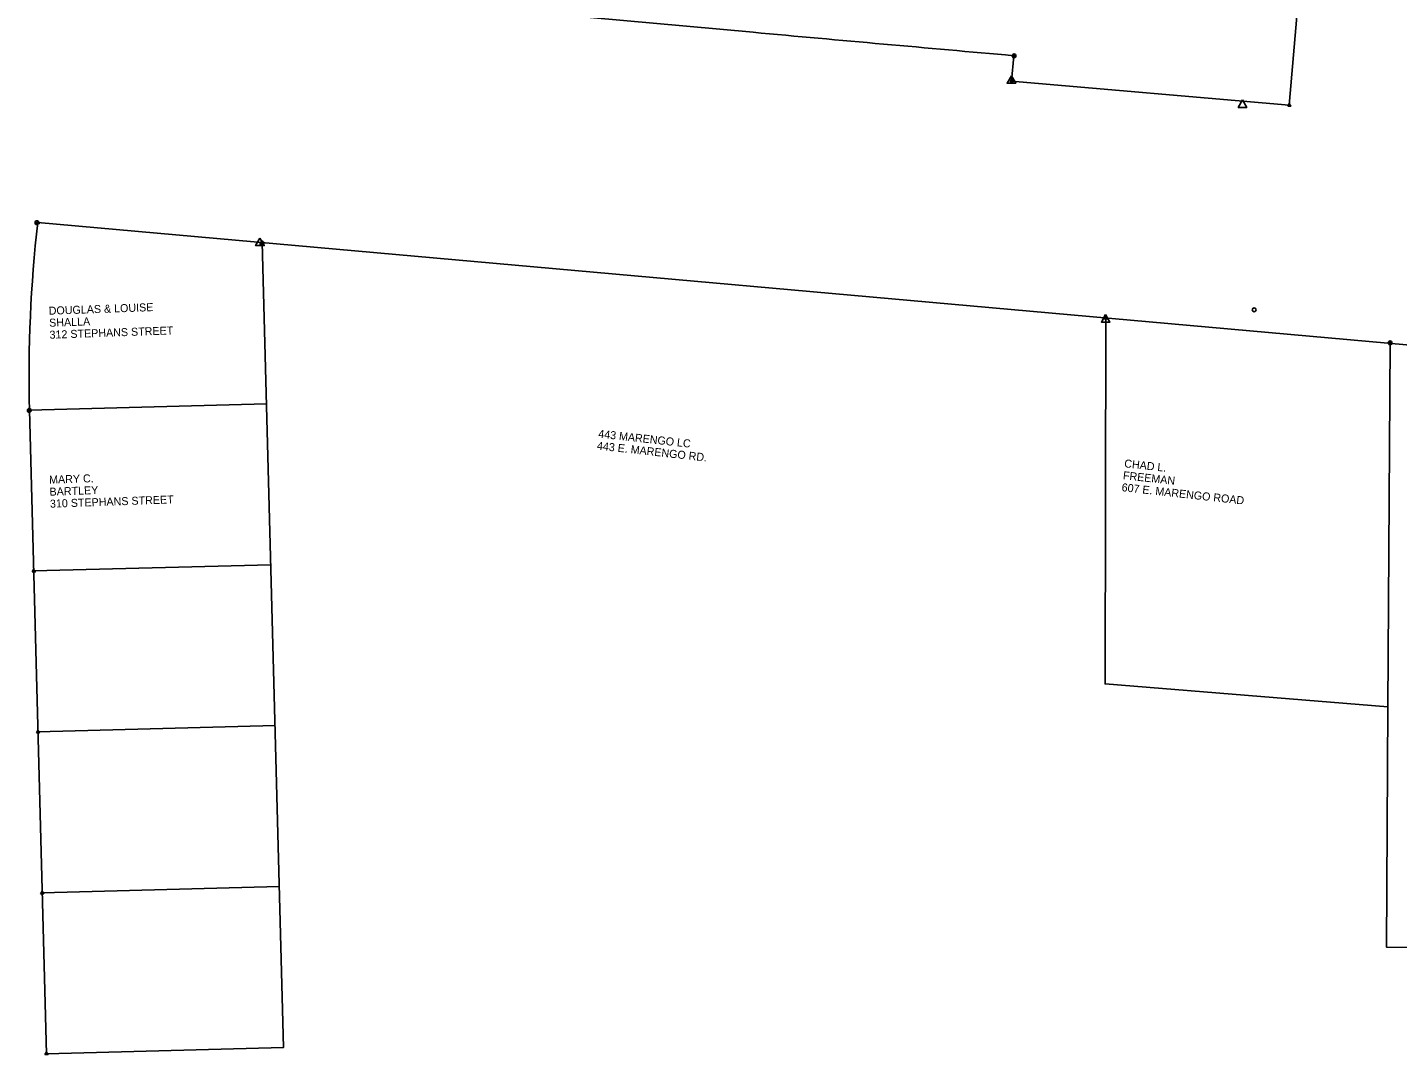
# Model space of a CAD drawing. Extents: x 20500076 to 20505422, y 7951999 to 7957351.
# Drawn here: x 20501774 to 20502582, y 7953327 to 7953933 of the extents above; entities that cross this region are included whole.
import ezdxf

# ---------------------------------------------------------------- set-up
doc = ezdxf.new("R2010")
doc.units = 0
for name, color, linetype in [('DisROW Existing', 7, 'Continuous'), ('DisROW Property Lines', 7, 'Continuous'), ('rowdsnSymbolsProposed', 7, 'Continuous'), ('SurControl', 7, 'Continuous'), ('SurSectionCorner', 7, 'Continuous'), ('Text', 7, 'Continuous')]:
    doc.layers.add(name, color=color, linetype=linetype)

msp = doc.modelspace()

# ---------------------------------------------------------------- linework, layer by layer
at = {"layer": 'DisROW Existing'}
for p, q in [((20502518.51, 7953887.39), (20502534.3, 7954075.17)), ((20501826.62, 7953964.54), (20502202.09, 7953930.47)), ((20502355.93, 7953916.67), (20502354.63, 7953901.73)), ((20502354.63, 7953901.73), (20502518.51, 7953887.39)), ((20501774.91, 7953707.55), (20501784.97, 7953327.68))]:
    msp.add_line(p, q, dxfattribs=at)
msp.add_lwpolyline([(20501779.83, 7953818.16), (20502611.84, 7953743.9), (20502613.1, 7953758.85)], dxfattribs=at)
for centre, radius, start, end in [((20508853.82, 8027226.31), 73597.05, 264.814512, 264.9347553), ((20502596.41, 7953726.45), 821.72, 173.59197, 181.33139)]:
    msp.add_arc(centre, radius, start, end, dxfattribs=at)
at = {"layer": 'DisROW Property Lines'}
for p, q in [((20501774.91, 7953707.54), (20501914.86, 7953711.25)), ((20501777.42, 7953612.57), (20501917.37, 7953616.28)), ((20501779.94, 7953517.61), (20501919.89, 7953521.31)), ((20501782.45, 7953422.64), (20501922.4, 7953426.35))]:
    msp.add_line(p, q, dxfattribs=at)
for points in [[(20501912.34, 7953806.33), (20501924.92, 7953331.38), (20501784.97, 7953327.67)], [(20502578, 7953746.92), (20502576.71, 7953532.3), (20502409.79, 7953545.93), (20502410.17, 7953761.9)], [(20502698.22, 7953736.42), (20502696.14, 7953389.92), (20502575.86, 7953390.64), (20502576.71, 7953532.3)]]:
    msp.add_lwpolyline(points, dxfattribs=at)
at = {"layer": 'rowdsnSymbolsProposed'}
for points in [[(20502355.93, 7953916.67), (20502355.93, 7953916.67)], [(20502354.63, 7953901.73), (20502354.63, 7953901.73)], [(20502518.51, 7953887.39), (20502518.51, 7953887.39)]]:
    msp.add_lwpolyline(points, dxfattribs=at)
at = {"layer": 'SurControl'}
for points in [[(20502354.51, 7953904.84), (20502357.06, 7953900.43), (20502351.96, 7953900.43)], [(20502490.93, 7953890.53), (20502493.48, 7953886.12), (20502488.38, 7953886.12)], [(20501910.98, 7953808.96), (20501913.53, 7953804.56), (20501908.43, 7953804.56)], [(20502410.16, 7953763.87), (20502412.71, 7953759.46), (20502407.61, 7953759.46)]]:
    msp.add_lwpolyline(points, close=True, dxfattribs=at)
for centre in [(20502356.11, 7953916.58), (20501779.37, 7953818.13), (20501912.17, 7953805.91), (20502497.81, 7953766.71), (20502578.01, 7953747.22), (20501774.87, 7953707.36)]:
    msp.add_circle(centre, 1.12, dxfattribs=at)
at = {"layer": 'SurSectionCorner'}
for points in [[(20502355.01, 7953916.14), (20502356.84, 7953916.14), (20502355.93, 7953917.73)], [(20502353.71, 7953901.2), (20502355.54, 7953901.2), (20502354.63, 7953902.78)], [(20502517.59, 7953886.86), (20502519.42, 7953886.86), (20502518.51, 7953888.44)], [(20501778.91, 7953817.63), (20501780.74, 7953817.63), (20501779.83, 7953819.22)], [(20501911.43, 7953805.8), (20501913.25, 7953805.8), (20501912.34, 7953807.39)], [(20502409.25, 7953761.37), (20502411.08, 7953761.37), (20502410.17, 7953762.96)], [(20502577.08, 7953746.4), (20502578.91, 7953746.4), (20502578, 7953747.98)], [(20501773.99, 7953707.01), (20501775.82, 7953707.01), (20501774.91, 7953708.59)], [(20501776.51, 7953612.04), (20501778.34, 7953612.04), (20501777.42, 7953613.63)], [(20501779.03, 7953517.08), (20501780.85, 7953517.08), (20501779.94, 7953518.66)], [(20501781.54, 7953422.11), (20501783.37, 7953422.11), (20501782.46, 7953423.69)], [(20501784.06, 7953327.14), (20501785.88, 7953327.14), (20501784.97, 7953328.73)]]:
    msp.add_lwpolyline(points, close=True, dxfattribs=at)

# ---------------------------------------------------------------- texts
at = {"layer": 'Text'}
for s, height, rotation, p in [('DOUGLAS & LOUISE', 4.7244, 2.02478, (20501786.4, 7953763.77)), ('SHALLA', 4.724, 2.02478, (20501786.65, 7953756.69)), ('312 STEPHANS STREET', 4.7244, 2.02478, (20501786.9, 7953749.61)), ('443 MARENGO LC', 4.7244, 353.70825, (20502110.51, 7953691.32)), ('443 E. MARENGO RD.', 4.7244, 353.70825, (20502109.73, 7953684.28)), ('CHAD L.', 4.724, 353.70825, (20502420.96, 7953673.79)), ('MARY C.', 4.724, 2.02478, (20501786.64, 7953664.04)), ('FREEMAN', 4.724, 353.70825, (20502420.19, 7953666.75)), ('BARTLEY', 4.724, 2.02478, (20501786.89, 7953656.96)), ('607 E. MARENGO ROAD', 4.7244, 353.70825, (20502419.41, 7953659.7)), ('310 STEPHANS STREET', 4.7244, 2.02478, (20501787.14, 7953649.88))]:
    msp.add_text(s, height=height, rotation=rotation, dxfattribs=at).set_placement(p)

doc.saveas('drawing.dxf')
